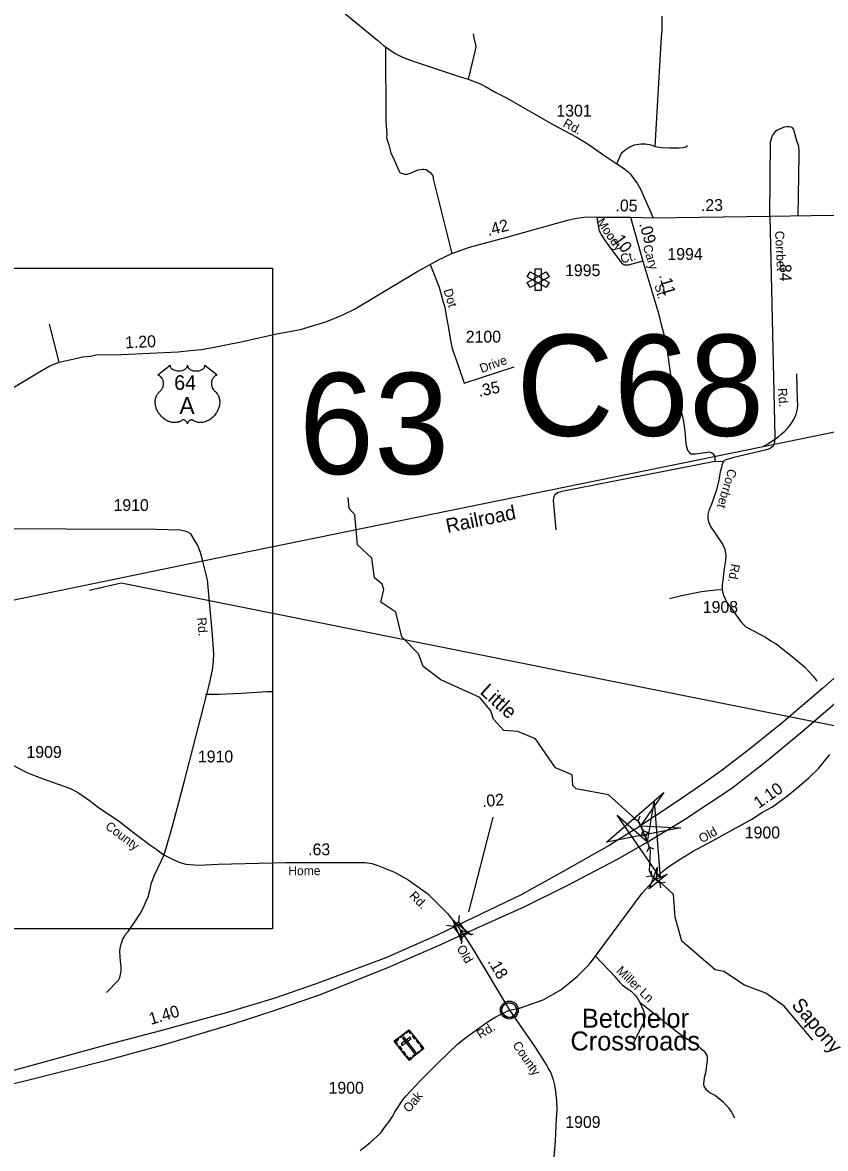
# Model space of a CAD drawing. Extents: x 2220236 to 2384410, y 720751 to 894131.
# Drawn here: x 2286022 to 2294491, y 800133 to 812018 of the extents above; entities that cross this region are included whole.
import ezdxf

# ---------------------------------------------------------------- set-up
doc = ezdxf.new("R2010")
doc.units = 0
doc.layers.add('Default', color=7, linetype='Continuous')

msp = doc.modelspace()

# ---------------------------------------------------------------- linework, layer by layer
at = {"layer": 'Default'}
for p, q in [((2292434, 809962), (2292566, 809498)), ((2292434, 809962), (2292674, 809957)), ((2292674, 809957), (2293905, 809976)), ((2286409, 808432), (2286305, 808833)), ((2293324, 807386), (2293417, 807389)), ((2290728, 802632), (2290985, 803629)), ((2292466, 803611), (2292515, 803595)), ((2292533, 803642), (2292515, 803595)), ((2292515, 803595), (2292567, 803486)), ((2292548, 803438), (2292567, 803486)), ((2292615, 803470), (2292567, 803486)), ((2292617, 803472), (2292593, 803427)), ((2292547, 803448), (2292593, 803427)), ((2292593, 803427), (2292633, 803313)), ((2292610, 803268), (2292633, 803313)), ((2292680, 803292), (2292633, 803313)), ((2292605, 803003), (2292655, 803010)), ((2292651, 803061), (2292655, 803010)), ((2292655, 803010), (2292749, 802935)), ((2292800, 802942), (2292749, 802935)), ((2292754, 802884), (2292749, 802935)), ((2290628, 802592), (2290619, 802524)), ((2290495, 802490), (2290563, 802481)), ((2290711, 802404), (2290780, 802395)), ((2290657, 802362), (2290648, 802294))]:
    msp.add_line(p, q, dxfattribs=at)
for points in [[(2289201, 812301), (2289771, 811830), (2289828, 811777), (2289850, 811763), (2289951, 811690), (2290031, 811651), (2290141, 811612), (2290627, 811449), (2290723, 811419), (2290843, 811375), (2290906, 811343), (2291016, 811280), (2291128, 811223), (2291623, 810938), (2291860, 810810), (2291987, 810736), (2292154, 810617), (2292250, 810556), (2292290, 810528), (2292361, 810481), (2292407, 810446), (2292431, 810422), (2292508, 810317), (2292545, 810253), (2292674, 809957)], [(2292695, 810710), (2292762, 811868), (2292767, 811930), (2292768, 812004), (2292768, 812084)], [(2290774, 811900), (2290785, 811844), (2290795, 811798), (2290799, 811788), (2290802, 811762), (2290792, 811714), (2290723, 811419)], [(2289850, 811763), (2289853, 810976), (2289863, 810838), (2289861, 810800), (2289884, 810726), (2289898, 810686), (2289908, 810638), (2289929, 810600), (2289990, 810457), (2290002, 810435), (2290016, 810427), (2290056, 810418), (2290079, 810416), (2290102, 810424), (2290194, 810465), (2290222, 810467), (2290238, 810471), (2290250, 810471), (2290280, 810466), (2290320, 810434), (2290347, 810406), (2290353, 810388), (2290353, 810368), (2290549, 809579)], [(2293905, 809976), (2293910, 810758), (2293933, 810826), (2293951, 810846), (2293968, 810874), (2293986, 810886), (2294060, 810919), (2294082, 810921), (2294108, 810921), (2294124, 810918), (2294134, 810912), (2294154, 810888), (2294181, 810784), (2294192, 810752), (2294202, 810728), (2294210, 810675), (2294211, 810615), (2294201, 809981)], [(2292290, 810528), (2292335, 810631), (2292351, 810651), (2292377, 810675), (2292421, 810704), (2292477, 810728), (2292544, 810739), (2292594, 810739), (2292648, 810726), (2292695, 810710)], [(2292695, 810710), (2292761, 810699), (2292847, 810696), (2292907, 810696), (2292949, 810695), (2292991, 810699), (2293018, 810707), (2293036, 810720)], [(2290322, 809463), (2290409, 809514), (2290549, 809579), (2290737, 809647), (2291130, 809752), (2291659, 809901), (2291772, 809932), (2291866, 809953), (2291970, 809966), (2292084, 809963), (2292186, 809964), (2292434, 809962)], [(2292170, 809714), (2292124, 809783), (2292107, 809815), (2292103, 809835), (2292084, 809963)], [(2293905, 809976), (2294557, 809984), (2295384, 809962), (2295595, 809920), (2295810, 809842), (2297438, 809503), (2297569, 809486), (2297695, 809476), (2297855, 809473)], [(2293905, 809976), (2293957, 807645), (2293953, 807588), (2293948, 807566)], [(2292566, 809498), (2292411, 809458), (2292376, 809456), (2292365, 809460), (2292350, 809470), (2292338, 809484), (2292247, 809609), (2292170, 809714)], [(2277171, 809424), (2288660, 809424), (2288660, 802451), (2277171, 802451), (2277171, 809424)], [(2284552, 807341), (2286202, 808332), (2286309, 808393), (2286409, 808432), (2286566, 808470), (2286660, 808489), (2286738, 808497), (2286796, 808510), (2286870, 808513), (2286992, 808512), (2287663, 808542), (2287795, 808555), (2287907, 808568), (2288009, 808583), (2288168, 808615), (2288330, 808648), (2288514, 808690), (2288701, 808732), (2288953, 808778), (2289082, 808815), (2289222, 808858), (2289399, 808932), (2289524, 808993), (2290193, 809395), (2290322, 809463)], [(2290322, 809463), (2290416, 809225), (2290460, 809066), (2290477, 809012), (2290483, 808964), (2290495, 808904), (2290510, 808814), (2290531, 808684), (2290553, 808576), (2290621, 808388), (2290679, 808212), (2291209, 808385)], [(2292566, 809498), (2292723, 808971), (2292729, 808948)], [(2292729, 808948), (2292760, 808818), (2292785, 808728), (2292821, 808558), (2292855, 808297), (2292921, 808066), (2292948, 807990), (2292969, 807916), (2292985, 807846), (2293009, 807707), (2293015, 807617), (2293022, 807553), (2293037, 807505), (2293057, 807475), (2293075, 807467), (2293121, 807466), (2293267, 807485), (2293285, 807481), (2293303, 807469), (2293311, 807462), (2293319, 807446), (2293323, 807432), (2293324, 807386)], [(2292592, 803356), (2293004, 803604), (2293503, 803938), (2293873, 804224), (2294268, 804551), (2294567, 804812), (2294780, 805008), (2294960, 805192), (2295496, 805771), (2295825, 806170), (2295961, 806343), (2296882, 807532), (2297484, 808294), (2297676, 808537), (2297737, 808613)], [(2297555, 808535), (2297325, 808258), (2296708, 807459), (2296006, 806559), (2295742, 806240), (2295564, 806033), (2295376, 805844), (2294852, 805335), (2294464, 804992), (2294032, 804624), (2293708, 804361), (2293414, 804136), (2293195, 803979), (2292894, 803773), (2292503, 803515), (2292211, 803331), (2291723, 803055), (2291281, 802811), (2290606, 802486)], [(2293834, 807542), (2293889, 807573), (2293927, 807599), (2293995, 807646), (2294025, 807674), (2294064, 807705), (2294098, 807743), (2294127, 807777), (2294157, 807827), (2294182, 807884), (2294194, 807926), (2294198, 807974), (2294197, 808040), (2294188, 808309)], [(2293834, 807542), (2296007, 807989), (2296926, 808182), (2297331, 808265), (2297410, 808281), (2297485, 808295)], [(2273202, 803292), (2287925, 806335), (2293834, 807542)], [(2293948, 807566), (2293936, 807543), (2293922, 807531), (2293900, 807519), (2293854, 807503), (2293525, 807426), (2293441, 807401), (2293417, 807389), (2293398, 807347), (2293394, 807322), (2293382, 807276), (2293365, 807188), (2293342, 807086), (2293282, 806914), (2293266, 806879), (2293249, 806823), (2293249, 806785), (2293256, 806747), (2293278, 806700), (2293406, 806513), (2293416, 806487), (2293428, 806461), (2293434, 806431), (2293439, 806393), (2293435, 806341), (2293418, 806233), (2293407, 806125), (2293402, 806089), (2293400, 806035)], [(2293324, 807386), (2291709, 807069), (2291665, 807054), (2291649, 807044), (2291638, 807032), (2291626, 807012), (2291620, 806978), (2291647, 806662)], [(2294359, 801277), (2294056, 801634), (2293863, 801773), (2293638, 801856), (2293420, 802002), (2293328, 802020), (2292975, 802322), (2292906, 802573), (2292887, 802813), (2292770, 802927), (2292702, 802973), (2292658, 803013), (2292635, 803061), (2292646, 803273), (2292637, 803306), (2292613, 803370), (2292560, 803498), (2292541, 803540), (2292521, 803579), (2292203, 803867), (2291861, 803930), (2291827, 803963), (2291818, 804078), (2291642, 804151), (2291431, 804457), (2291247, 804533), (2291097, 804546), (2290988, 804663), (2290962, 804752), (2290844, 804895), (2290434, 805081), (2290249, 805222), (2290198, 805355), (2290022, 805535), (2289961, 805793), (2289802, 805901), (2289834, 806035), (2289816, 806091), (2289733, 806158), (2289705, 806365), (2289554, 806506), (2289526, 806822), (2289467, 806888), (2289458, 807003)], [(2287513, 803234), (2287527, 803269), (2287609, 803551), (2287730, 804013), (2287874, 804573), (2287995, 805039), (2288030, 805202), (2288036, 805286), (2288039, 805351), (2288026, 805554), (2287973, 806135), (2287924, 806333), (2287899, 806425), (2287870, 806497), (2287834, 806562), (2287798, 806620), (2287758, 806641), (2287690, 806659), (2287423, 806666), (2285536, 806675), (2285246, 806680), (2285002, 806680), (2284671, 806690), (2284558, 806694)], [(2286729, 806028), (2287062, 806105), (2296043, 804305)], [(2292847, 805938), (2292973, 805969), (2293095, 805996), (2293185, 806011), (2293330, 806030), (2293400, 806035)], [(2293400, 806035), (2293404, 806011), (2293415, 805975), (2293429, 805941), (2293455, 805892), (2293506, 805824), (2293601, 805687), (2293650, 805638), (2293857, 805530), (2293915, 805490), (2293971, 805459), (2294175, 805299), (2294272, 805212), (2294366, 805115), (2294391, 805080), (2294401, 805067)], [(2287951, 804928), (2288097, 804928), (2288327, 804938), (2288599, 804956), (2288653, 804957)], [(2291157, 801592), (2291265, 801613), (2291512, 801701), (2291701, 801809), (2291873, 801949), (2292002, 802080), (2292559, 802827), (2292719, 803004), (2292769, 803053), (2292830, 803101), (2292957, 803188), (2293003, 803215), (2293094, 803271), (2293301, 803379), (2293715, 803609), (2293828, 803684), (2293931, 803741), (2294029, 803810), (2294094, 803859), (2294213, 803956), (2294316, 804045), (2294417, 804144), (2294538, 804291)], [(2285905, 804186), (2286066, 804101), (2286138, 804072), (2286277, 804021), (2286397, 803980), (2286467, 803953), (2286535, 803930), (2286612, 803888), (2286728, 803807), (2286819, 803736), (2287045, 803583), (2287178, 803478), (2287376, 803331), (2287429, 803296), (2287457, 803275), (2287513, 803234)], [(2290669, 802396), (2291313, 802682), (2291773, 802912), (2292291, 803182), (2292592, 803356)], [(2286907, 801778), (2287034, 801909), (2287048, 801939), (2287055, 801971), (2287061, 802005), (2287063, 802049), (2287054, 802111), (2287047, 802209), (2287053, 802249), (2287059, 802277), (2287078, 802335), (2287094, 802362), (2287105, 802388), (2287135, 802424), (2287208, 802525), (2287259, 802607), (2287293, 802669), (2287324, 802735), (2287348, 802790), (2287365, 802856), (2287382, 802936), (2287394, 802962), (2287411, 803012), (2287519, 803241)], [(2287513, 803234), (2287610, 803182), (2287683, 803153), (2287744, 803134), (2287882, 803124), (2288084, 803134), (2288795, 803153), (2289631, 803153), (2289705, 803142), (2289771, 803120), (2289947, 803049), (2290091, 802967), (2290298, 802821), (2290504, 802612), (2290606, 802486)], [(2283646, 800223), (2284195, 800390), (2284784, 800541), (2285489, 800715), (2286047, 800848), (2286924, 801067), (2287517, 801229), (2288256, 801451), (2288666, 801586), (2289153, 801755), (2289869, 802040), (2290433, 802286), (2290669, 802396)], [(2290606, 802486), (2290395, 802385), (2289855, 802146), (2289107, 801866), (2288685, 801719), (2288169, 801564), (2287479, 801375), (2286901, 801222), (2286018, 800980), (2285465, 800833), (2284762, 800654), (2283991, 800433), (2283647, 800325)], [(2290606, 802486), (2290669, 802396)], [(2290669, 802396), (2290688, 802369), (2290776, 802234), (2291157, 801592)], [(2292065, 802162), (2292269, 801948), (2292320, 801889), (2292348, 801861), (2292398, 801822), (2292440, 801794), (2292485, 801750), (2292503, 801729), (2292531, 801681)], [(2292531, 801681), (2292568, 801595), (2292581, 801556), (2292585, 801521), (2292570, 801455), (2292550, 801419), (2292483, 801283), (2292474, 801257), (2292466, 801247), (2292468, 801235), (2292480, 801191)], [(2292531, 801681), (2292828, 801442), (2292928, 801365), (2293037, 801286), (2293103, 801251), (2293146, 801219), (2293174, 801191), (2293210, 801160), (2293230, 801132), (2293239, 801116), (2293243, 801094), (2293245, 801064), (2293232, 800980), (2293226, 800930), (2293213, 800878), (2293207, 800846), (2293205, 800814), (2293208, 800792), (2293230, 800760), (2293276, 800722), (2293330, 800693), (2293413, 800626), (2293470, 800562), (2293500, 800515), (2293532, 800457)], [(2289582, 800112), (2289637, 800154), (2289685, 800193), (2289798, 800296), (2289852, 800370), (2289888, 800416), (2289923, 800471), (2289953, 800523), (2290033, 800648), (2290067, 800690), (2290117, 800743), (2290222, 800854), (2290327, 800960), (2290401, 801032), (2290612, 801236), (2290694, 801302), (2290809, 801386), (2290883, 801438), (2290956, 801488), (2291014, 801523), (2291119, 801576), (2291157, 801592)], [(2291157, 801592), (2291431, 801195), (2291550, 801014), (2291575, 800966), (2291595, 800930), (2291620, 800857), (2291632, 800803), (2291643, 800735), (2291654, 800639), (2291659, 800537), (2291652, 800445), (2291640, 800215), (2291622, 799999)]]:
    msp.add_lwpolyline(points, dxfattribs=at)
for points in [[(2291491, 809189), (2291430, 809189), (2291430, 809420), (2291491, 809420)], [(2291376, 809220), (2291346, 809273), (2291546, 809388), (2291576, 809335)], [(2291576, 809273), (2291546, 809220), (2291346, 809335), (2291376, 809388)], [(2287578, 808401), (2287578, 808396), (2287579, 808389), (2287580, 808386), (2287583, 808380), (2287588, 808373), (2287595, 808365), (2287603, 808359), (2287608, 808356), (2287617, 808351), (2287627, 808347), (2287638, 808344), (2287649, 808341), (2287661, 808340), (2287674, 808340), (2287687, 808341), (2287701, 808344), (2287708, 808345), (2287716, 808348), (2287723, 808351), (2287730, 808355), (2287737, 808359), (2287741, 808362), (2287748, 808369), (2287754, 808376), (2287756, 808379), (2287758, 808383), (2287761, 808391), (2287761, 808394), (2287762, 808401), (2287762, 808395), (2287763, 808392), (2287764, 808388), (2287765, 808384), (2287768, 808379), (2287771, 808374), (2287777, 808367), (2287780, 808364), (2287784, 808361), (2287792, 808355), (2287803, 808350), (2287808, 808348), (2287813, 808346), (2287819, 808344), (2287826, 808343), (2287833, 808341), (2287840, 808340), (2287847, 808340), (2287852, 808340), (2287859, 808340), (2287866, 808340), (2287872, 808341), (2287880, 808342), (2287886, 808343), (2287893, 808345), (2287900, 808348), (2287906, 808351), (2287914, 808355), (2287921, 808359), (2287926, 808363), (2287931, 808368), (2287937, 808374), (2287940, 808378), (2287942, 808383), (2287944, 808388), (2287945, 808393), (2287946, 808398), (2287946, 808401), (2288074, 808299), (2288071, 808298), (2288064, 808294), (2288059, 808291), (2288050, 808285), (2288046, 808282), (2288042, 808278), (2288039, 808274), (2288036, 808271), (2288032, 808265), (2288029, 808260), (2288026, 808255), (2288023, 808250), (2288019, 808239), (2288017, 808233), (2288016, 808227), (2288015, 808216), (2288014, 808210), (2288014, 808205), (2288015, 808199), (2288015, 808194), (2288016, 808188), (2288017, 808183), (2288019, 808177), (2288021, 808170), (2288024, 808163), (2288030, 808152), (2288037, 808140), (2288042, 808134), (2288048, 808128), (2288056, 808122), (2288060, 808118), (2288065, 808113), (2288073, 808104), (2288076, 808099), (2288080, 808094), (2288083, 808089), (2288086, 808084), (2288088, 808079), (2288093, 808068), (2288096, 808057), (2288097, 808051), (2288100, 808039), (2288101, 808033), (2288102, 808020), (2288102, 808005), (2288101, 807991), (2288098, 807975), (2288096, 807965), (2288092, 807953), (2288089, 807944), (2288083, 807929), (2288078, 807918), (2288071, 807906), (2288067, 807898), (2288061, 807890), (2288054, 807881), (2288047, 807871), (2288037, 807861), (2288029, 807853), (2288019, 807844), (2288013, 807839), (2288005, 807832), (2287993, 807825), (2287981, 807818), (2287971, 807813), (2287962, 807809), (2287951, 807805), (2287932, 807799), (2287925, 807798), (2287917, 807797), (2287909, 807796), (2287902, 807795), (2287892, 807795), (2287882, 807796), (2287872, 807798), (2287863, 807800), (2287852, 807803), (2287843, 807806), (2287834, 807811), (2287818, 807821), (2287813, 807823), (2287810, 807824), (2287804, 807824), (2287799, 807823), (2287793, 807821), (2287789, 807819), (2287784, 807816), (2287781, 807813), (2287776, 807809), (2287773, 807805), (2287771, 807802), (2287766, 807795), (2287765, 807792), (2287763, 807788), (2287762, 807781), (2287760, 807789), (2287757, 807795), (2287755, 807799), (2287752, 807803), (2287747, 807808), (2287743, 807812), (2287738, 807816), (2287733, 807819), (2287729, 807822), (2287725, 807823), (2287721, 807824), (2287717, 807824), (2287714, 807824), (2287709, 807823), (2287704, 807819), (2287698, 807815), (2287692, 807812), (2287685, 807808), (2287680, 807805), (2287674, 807803), (2287666, 807801), (2287658, 807799), (2287650, 807797), (2287643, 807796), (2287635, 807795), (2287628, 807795), (2287621, 807795), (2287615, 807795), (2287607, 807796), (2287597, 807798), (2287589, 807799), (2287580, 807802), (2287572, 807804), (2287562, 807808), (2287551, 807813), (2287543, 807817), (2287530, 807825), (2287515, 807835), (2287503, 807844), (2287495, 807852), (2287483, 807864), (2287476, 807872), (2287464, 807887), (2287457, 807898), (2287452, 807905), (2287446, 807918), (2287442, 807926), (2287437, 807937), (2287433, 807947), (2287430, 807957), (2287428, 807964), (2287426, 807975), (2287424, 807982), (2287423, 807993), (2287422, 808004), (2287422, 808015), (2287422, 808024), (2287423, 808034), (2287425, 808044), (2287427, 808054), (2287429, 808060), (2287432, 808068), (2287435, 808077), (2287439, 808086), (2287443, 808093), (2287449, 808100), (2287454, 808107), (2287460, 808114), (2287467, 808120), (2287473, 808126), (2287481, 808133), (2287485, 808137), (2287489, 808143), (2287493, 808149), (2287496, 808154), (2287500, 808162), (2287502, 808167), (2287505, 808176), (2287507, 808182), (2287508, 808190), (2287509, 808197), (2287509, 808206), (2287509, 808214), (2287508, 808223), (2287507, 808231), (2287505, 808239), (2287501, 808247), (2287498, 808254), (2287494, 808262), (2287488, 808270), (2287482, 808276), (2287477, 808282), (2287471, 808286), (2287466, 808290), (2287460, 808294), (2287453, 808297), (2287449, 808299)], [(2292966, 803516), (2292180, 803366), (2292786, 803889), (2292541, 803540)], [(2292684, 803791), (2292747, 802993), (2292294, 803652), (2292613, 803370)], [(2292820, 803027), (2292630, 802875), (2292719, 803102), (2292702, 802973)], [(2290656, 802313), (2290563, 802538), (2290756, 802389), (2290637, 802441)], [(2290619, 802524), (2290712, 802404), (2290656, 802361), (2290563, 802481)], [(2291079, 801606), (2291080, 801612), (2291082, 801618), (2291085, 801625), (2291088, 801631), (2291091, 801637), (2291095, 801642), (2291099, 801646), (2291103, 801651), (2291109, 801656), (2291114, 801659), (2291119, 801662), (2291124, 801665), (2291130, 801667), (2291135, 801669), (2291140, 801670), (2291145, 801671), (2291149, 801671), (2291155, 801672), (2291159, 801672), (2291165, 801671), (2291170, 801671), (2291175, 801670), (2291180, 801668), (2291185, 801666), (2291192, 801663), (2291198, 801660), (2291203, 801656), (2291208, 801652), (2291212, 801649), (2291216, 801645), (2291220, 801640), (2291223, 801635), (2291226, 801630), (2291228, 801625), (2291230, 801620), (2291232, 801615), (2291233, 801611), (2291234, 801605), (2291235, 801600), (2291235, 801594), (2291235, 801588), (2291234, 801582), (2291233, 801577), (2291232, 801571), (2291230, 801565), (2291228, 801560), (2291224, 801554), (2291221, 801549), (2291218, 801544), (2291213, 801539), (2291208, 801534), (2291203, 801530), (2291198, 801527), (2291194, 801524), (2291187, 801521), (2291180, 801518), (2291174, 801517), (2291167, 801515), (2291163, 801515), (2291158, 801515), (2291153, 801515), (2291148, 801515), (2291143, 801516), (2291137, 801517), (2291132, 801518), (2291127, 801520), (2291123, 801522), (2291119, 801524), (2291112, 801529), (2291106, 801533), (2291101, 801537), (2291097, 801542), (2291094, 801546), (2291091, 801550), (2291087, 801557), (2291085, 801561), (2291083, 801565), (2291081, 801573), (2291079, 801580), (2291078, 801585), (2291078, 801592), (2291078, 801596), (2291079, 801603)], [(2289942, 801264), (2290098, 801387), (2290256, 801187), (2290099, 801064)], [(2290000, 801310), (2290041, 801342), (2290048, 801333), (2290007, 801301)], [(2290125, 801353), (2290116, 801346), (2290096, 801371), (2290065, 801346), (2290058, 801355), (2290098, 801387)], [(2290161, 801288), (2290135, 801322), (2290144, 801329), (2290170, 801295)], [(2289969, 801230), (2289978, 801237), (2289958, 801262), (2289990, 801287), (2289983, 801296), (2289942, 801264)], [(2290015, 801171), (2289988, 801206), (2289997, 801213), (2290023, 801178)], [(2290016, 801236), (2290028, 801221), (2290120, 801294), (2290109, 801308)], [(2290046, 801308), (2290031, 801297), (2290156, 801137), (2290171, 801149)], [(2290202, 801237), (2290175, 801271), (2290184, 801278), (2290211, 801244)], [(2290230, 801166), (2290223, 801175), (2290240, 801189), (2290215, 801221), (2290224, 801228), (2290256, 801187)], [(2290056, 801119), (2290029, 801153), (2290038, 801160), (2290065, 801126)], [(2290125, 801084), (2290118, 801093), (2290101, 801080), (2290076, 801111), (2290067, 801104), (2290099, 801064)], [(2290137, 801108), (2290204, 801161), (2290211, 801152), (2290144, 801099)]]:
    msp.add_lwpolyline(points, close=True, dxfattribs=at)
for centre, radius in [((2291157, 801594), 94.3), ((2291156, 801594), 76.7)]:
    msp.add_circle(centre, radius, dxfattribs=at)

# ---------------------------------------------------------------- texts
for s, height, p in [('1301', 125, (2291653, 811026)), ('1994', 125, (2292824, 809513)), ('1995', 125, (2291745, 809341)), ('2100', 125, (2290697, 808640)), ('C68', 1066.3, (2291229, 807656)), ('63', 1066.3, (2288937, 807253)), ('64', 155, (2287622, 808140)), ('A', 180, (2287677, 807885)), ('1910', 125, (2286982, 806862)), ('1908', 125, (2293197, 805787)), ('1909', 125, (2286064, 804256)), ('1910', 125, (2287872, 804208)), ('1900', 125, (2293640, 803406)), ('Betchelor', 200, (2291922, 801408)), ('Crossroads', 200, (2291801, 801168)), ('1900', 125, (2289250, 800711)), ('1909', 125, (2291747, 800350))]:
    msp.add_text(s, height=height, dxfattribs=at).set_placement(p)
for s, height, rotation, p in [('Rd.', 95, 331.6934, (2291715, 810926)), ('.05', 125, 358.639, (2292275, 810027)), ('.23', 125, 0.9074, (2293178, 810027)), ('.42', 125, 14.9392, (2290936, 809765)), ('Moody', 95, 304.3415, (2292073, 809913)), ('.09', 125, 285.8949, (2292525, 809894)), ('.10', 125, 306.1197, (2292223, 809763)), ('Corrbet', 95, 272.7157, (2293959, 809817)), ('Cary', 95, 286.6002, (2292564, 809658)), ('Ct.', 95, 14.2531, (2292341, 809475)), ('.84', 125, 271.2732, (2294005, 809515)), ('.11', 125, 285.8949, (2292734, 809350)), ('Dot', 95, 286.9157, (2290461, 809193)), ('St.', 95, 285.971, (2292686, 809244)), ('1.20', 125, 2.5839, (2287107, 808579)), ('Drive', 95, 19.8479, (2290864, 808318)), ('.35', 125, 11.969, (2290839, 808066)), ('Rd.', 95, 274.3181, (2293989, 808156)), ('Corrbet', 95, 253.3216, (2293467, 807315)), ('Railroad', 150, 11.6395, (2290504, 806629)), ('Rd.', 95, 259.9601, (2293497, 806311)), ('Rd.', 95, 274.5216, (2287865, 805735)), ('Little', 150, 317.6706, (2290838, 804942)), ('1.10', 125, 35.316, (2293788, 803716)), ('.02', 125, 5.2076, (2290874, 803736)), ('County', 95, 323.2963, (2286887, 803516)), ('Old', 95, 29.0568, (2293187, 803354)), ('.63', 125, 359.9859, (2289035, 803228)), ('Home', 95, 0.2649, (2288826, 803017)), ('Rd.', 95, 315.3408, (2290094, 802792)), ('Old', 95, 300.2384, (2290598, 802247)), ('.18', 125, 300.7061, (2290924, 802107)), ('Miller Ln', 95, 316.1629, (2292278, 802000)), ('Sapony', 150, 310.313, (2294126, 801643)), ('1.40', 125, 16.6818, (2287376, 801437)), ('Rd.', 95, 31.0816, (2290849, 801287)), ('County', 95, 304.5365, (2291186, 801224)), ('Oak', 95, 50.2158, (2290100, 800505))]:
    msp.add_text(s, height=height, rotation=rotation, dxfattribs=at).set_placement(p)

doc.saveas('drawing.dxf')
